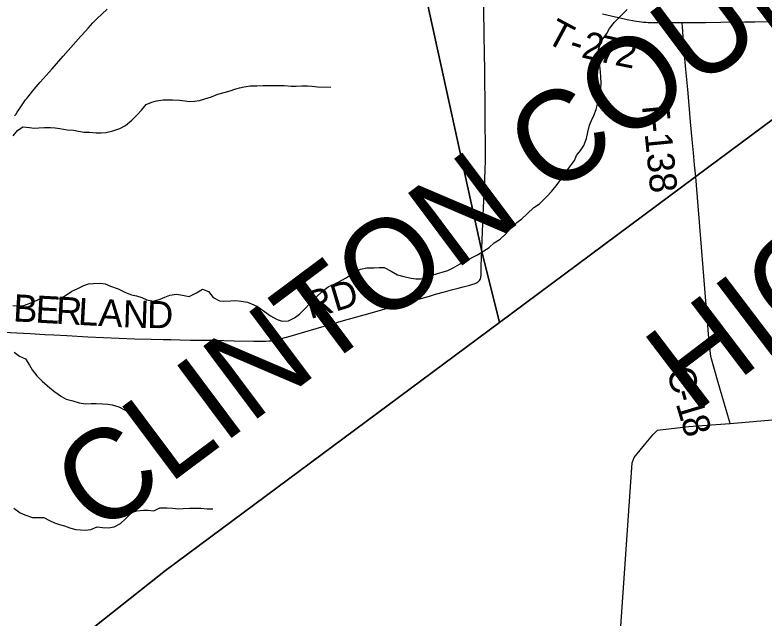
# Model space of a CAD drawing. Extents: x 0 to 48.6, y 0 to 22.
# Drawn here: x 5.524 to 7.09, y 17.154 to 18.416 of the extents above; entities that cross this region are included whole.
import ezdxf

# ---------------------------------------------------------------- set-up
doc = ezdxf.new("R2010")
doc.units = 0
for name, color, linetype in [('GM_X_Corporation', 7, 'Continuous'), ('GM_X_County_Road', 7, 'Continuous'), ('GM_X_County_Road_Text', 7, 'Continuous'), ('GM_X_County_Text', 7, 'Continuous'), ('GM_X_Minor_River', 7, 'Continuous'), ('GM_X_Township_Road', 7, 'Continuous'), ('GM_X_Township_Road_Text', 7, 'Continuous')]:
    doc.layers.add(name, color=color, linetype=linetype)

msp = doc.modelspace()

# ---------------------------------------------------------------- linework, layer by layer
at = {"layer": 'GM_X_Corporation'}
for points in [[(5.5264, 17.0064), (5.8387, 17.2541), (6.5365, 17.7727), (6.4996, 17.9212), (6.3396, 18.6531), (6.2759, 18.9159), (6.0412, 19.8859), (5.8236, 20.7829), (5.795, 20.9), (2.1, 20.9), (2.1, 14.1)], [(5.5264, 17.0064), (5.8387, 17.2541), (6.5365, 17.7727), (6.9471, 18.0777), (7.2261, 18.2847)]]:
    msp.add_lwpolyline(points, dxfattribs=at)
for points in [[(8.9, 19.5692), (8.9, 20.9), (5.795, 20.9), (5.8236, 20.7829), (6.0412, 19.8859), (6.2759, 18.9159), (6.3396, 18.6531), (6.4996, 17.9212), (6.5365, 17.7727), (6.9471, 18.0777), (7.2261, 18.2847), (8.5348, 19.2897)], [(5.0944, 14.1), (8.9, 14.1), (8.9, 19.5692), (8.5348, 19.2897), (7.2261, 18.2847), (6.9471, 18.0777), (6.5365, 17.7727), (5.8387, 17.2541), (5.5264, 17.0064), (4.6225, 16.3345), (4.044, 15.9033), (4.0346, 15.8959), (4.0398, 15.887), (4.3544, 15.3539), (4.4679, 15.1616), (4.7542, 14.6766)]]:
    msp.add_lwpolyline(points, close=True, dxfattribs=at)
at = {"layer": 'GM_X_County_Road'}
for points in [[(7.0193, 17.5612), (6.9943, 17.6472), (6.979, 17.7015), (6.9747, 17.7396), (6.9473, 18.0772)], [(6.2545, 16.2661), (6.3196, 16.2983), (6.3869, 16.3334), (6.4082, 16.3506), (6.4486, 16.3853), (6.4771, 16.4164), (6.644, 16.6404), (6.7584, 16.7938), (6.7668, 16.8095), (6.7711, 16.8557), (6.8142, 17.4789), (6.8183, 17.4898), (6.8434, 17.5207), (6.8575, 17.5377), (6.8672, 17.547), (6.9323, 17.5551), (7.0193, 17.5612), (7.1388, 17.5717)]]:
    msp.add_lwpolyline(points, dxfattribs=at)
at = {"layer": 'GM_X_Minor_River'}
for points in [[(5.8475, 17.8297), (5.8618, 17.8314), (5.874, 17.8298), (5.8883, 17.8266), (5.9032, 17.8348), (5.9158, 17.8419), (5.9287, 17.8373), (5.9384, 17.825), (5.9513, 17.8177), (5.9607, 17.8169), (5.9752, 17.8175), (5.9846, 17.8182), (5.9968, 17.8169), (6.0097, 17.8153), (6.0229, 17.8095), (6.0331, 17.8048), (6.0452, 17.7956), (6.058, 17.7864), (6.0719, 17.779), (6.0825, 17.7751), (6.0958, 17.7762), (6.108, 17.7825), (6.1187, 17.79), (6.1287, 17.7994), (6.1413, 17.8137), (6.1536, 17.8254), (6.1658, 17.8374), (6.1784, 17.8468), (6.1914, 17.8527), (6.2009, 17.8576), (6.2146, 17.865), (6.2261, 17.8721), (6.2368, 17.8789), (6.2463, 17.8837), (6.2592, 17.887), (6.274, 17.8869), (6.2854, 17.8872), (6.296, 17.8875), (6.31, 17.8797), (6.3232, 17.8724), (6.3368, 17.8685), (6.3524, 17.8649), (6.3618, 17.8637), (6.3717, 17.8636), (6.382, 17.8654), (6.3961, 17.8714), (6.4071, 17.8751), (6.417, 17.8776), (6.4291, 17.8809), (6.4402, 17.8869), (6.4543, 17.8951), (6.4658, 17.9015), (6.4783, 17.9078), (6.4909, 17.9138), (6.5043, 17.922), (6.5153, 17.9295), (6.526, 17.9389), (6.5379, 17.9468), (6.5494, 17.9569), (6.5597, 17.969), (6.5731, 17.9817), (6.5834, 17.9892), (6.5945, 17.9998), (6.6087, 18.0129), (6.6201, 18.0208), (6.6358, 18.0362), (6.6454, 18.0464), (6.655, 18.058), (6.665, 18.0716), (6.6723, 18.0814), (6.6792, 18.0916), (6.6938, 18.1112), (6.6981, 18.1214), (6.7065, 18.1324), (6.713, 18.1425), (6.7185, 18.1573), (6.7216, 18.1702), (6.7252, 18.1849), (6.7295, 18.1952), (6.7337, 18.2057), (6.7388, 18.2182), (6.7419, 18.2292), (6.7443, 18.2406), (6.747, 18.2508), (6.7487, 18.2622), (6.7491, 18.2735), (6.7485, 18.2853), (6.7478, 18.2967), (6.7464, 18.3096), (6.745, 18.321), (6.7432, 18.3305), (6.7437, 18.3431), (6.7476, 18.3537), (6.7518, 18.3635), (6.7611, 18.3771), (6.7665, 18.3873), (6.7776, 18.4004), (6.7914, 18.4144), (6.804, 18.4268)], [(5.8532, 18.2384), (5.8674, 18.2375), (5.8791, 18.2359), (5.889, 18.235), (5.8989, 18.2357), (5.9095, 18.2371), (5.9205, 18.2401), (5.9346, 18.2445), (5.9476, 18.2497), (5.9609, 18.2537), (5.9738, 18.257), (5.9833, 18.2604), (5.9932, 18.2629), (6.0027, 18.2655), (6.0156, 18.2677), (6.0297, 18.2675), (6.043, 18.2682), (6.0528, 18.2681), (6.0646, 18.2684), (6.0767, 18.2683), (6.0866, 18.2678), (6.101, 18.2669), (6.112, 18.2664), (6.1234, 18.2671), (6.1352, 18.2673), (6.1454, 18.2669), (6.1564, 18.2656), (6.1845, 18.2646)], [(5.5198, 18.1626), (5.529, 18.1743), (5.5405, 18.1817), (5.5542, 18.1804), (5.5637, 18.1787), (5.5739, 18.1798), (5.5853, 18.18), (5.5979, 18.1802), (5.6081, 18.1793), (5.6176, 18.1784), (5.6327, 18.1752), (5.6464, 18.175), (5.6563, 18.1726), (5.6684, 18.1702), (5.6794, 18.1704), (5.6938, 18.1691), (5.7041, 18.169), (5.714, 18.17), (5.7281, 18.1736), (5.7433, 18.1783), (5.7548, 18.1846), (5.7682, 18.1955), (5.7783, 18.2063), (5.7883, 18.2168), (5.7983, 18.2281), (5.8101, 18.2333), (5.8197, 18.2362), (5.8334, 18.2383), (5.8532, 18.2384)], [(5.5196, 17.8077), (5.5317, 17.8075), (5.5424, 17.8081), (5.5592, 17.814), (5.5702, 17.8192), (5.5821, 17.8251), (5.5927, 17.8253), (5.6052, 17.8221), (5.6189, 17.8223), (5.6296, 17.8286), (5.6423, 17.8383), (5.6549, 17.8435), (5.6679, 17.8498), (5.6774, 17.8531), (5.6881, 17.8541), (5.7025, 17.855), (5.7124, 17.8534), (5.7237, 17.8483), (5.7392, 17.8428), (5.7535, 17.8358), (5.7671, 17.8306), (5.7777, 17.8279), (5.7887, 17.8247), (5.7993, 17.82), (5.8137, 17.8168), (5.827, 17.8215), (5.837, 17.8252), (5.8475, 17.8297)], [(5.5224, 17.7101), (5.533, 17.7023), (5.5458, 17.6965), (5.554, 17.6831), (5.5595, 17.6735), (5.5693, 17.6609), (5.5805, 17.6497), (5.5963, 17.6358), (5.6068, 17.6277), (5.6211, 17.6177), (5.6309, 17.6122), (5.6445, 17.6086), (5.6578, 17.6043), (5.6714, 17.6026), (5.6832, 17.6028), (5.6938, 17.6031), (5.7075, 17.6021), (5.7177, 17.6016), (5.7272, 17.6004), (5.7408, 17.5964), (5.7544, 17.5894), (5.7665, 17.5866)], [(5.5215, 17.3844), (5.5346, 17.3743), (5.5445, 17.37), (5.5607, 17.3645), (5.5733, 17.3647), (5.5843, 17.3646), (5.5959, 17.358), (5.6065, 17.3536), (5.6167, 17.3497), (5.6273, 17.3469), (5.6383, 17.343), (5.6504, 17.3394), (5.6606, 17.3389), (5.6713, 17.3384), (5.6827, 17.3397), (5.6953, 17.3449), (5.7071, 17.344), (5.7192, 17.3431), (5.7314, 17.3448), (5.7444, 17.3519), (5.7551, 17.3616), (5.7679, 17.3751), (5.7782, 17.3787), (5.7922, 17.3801), (5.8021, 17.3796), (5.8142, 17.3783), (5.8265, 17.3846), (5.8413, 17.3845)], [(5.8413, 17.3845), (5.8528, 17.384), (5.8657, 17.3824), (5.8756, 17.3834), (5.8885, 17.384), (5.8995, 17.3843), (5.9124, 17.3838), (5.9253, 17.3826), (5.9374, 17.3828)]]:
    msp.add_lwpolyline(points, dxfattribs=at)
at = {"layer": 'GM_X_Township_Road'}
for points in [[(6.4999, 17.9207), (6.5002, 17.9274), (6.503, 17.997), (6.5043, 18.0274), (6.5051, 18.0521), (6.5059, 18.0645), (6.5064, 18.0744), (6.507, 18.0906), (6.5077, 18.1129), (6.5077, 18.1199), (6.5077, 18.1421), (6.5071, 18.1893), (6.5067, 18.2409), (6.5063, 18.2732), (6.506, 18.2949), (6.5051, 18.3409), (6.5048, 18.367), (6.5038, 18.4347), (6.5035, 18.4639), (6.503, 18.5086), (6.5031, 18.5229), (6.5032, 18.5391), (6.5032, 18.5489)], [(5.5227, 18.2047), (5.5253, 18.2078), (5.5285, 18.2122), (5.532, 18.2173), (5.5399, 18.2298), (5.5429, 18.2339), (5.5458, 18.2379), (5.5482, 18.241), (5.5503, 18.2438), (5.5533, 18.2474), (5.5641, 18.2607), (5.5763, 18.2748), (5.6013, 18.3032), (5.6248, 18.3297), (5.6511, 18.3595), (5.6618, 18.3715), (5.6709, 18.3818), (5.6766, 18.3883), (5.6867, 18.3994), (5.6949, 18.4079), (5.7162, 18.4278)], [(6.9186, 18.3989), (6.8896, 18.3989), (6.8573, 18.3991), (6.8522, 18.3993), (6.8474, 18.3995), (6.8427, 18.3998), (6.8381, 18.4002), (6.8338, 18.4007), (6.8288, 18.4013), (6.8233, 18.4022), (6.8184, 18.403), (6.8038, 18.4058), (6.7522, 18.4171)], [(7.1632, 18.4013), (7.1535, 18.4013), (7.1101, 18.4011), (7.071, 18.4006), (7.0499, 18.4004), (6.9996, 18.3996), (6.9673, 18.399), (6.9387, 18.3989), (6.9186, 18.3989)], [(6.9473, 18.0772), (6.9446, 18.1023), (6.9424, 18.1276), (6.9397, 18.1554), (6.9365, 18.1919), (6.9339, 18.2185), (6.9303, 18.26), (6.9266, 18.3014), (6.9246, 18.3249), (6.9207, 18.3701), (6.9192, 18.3911), (6.9186, 18.3989)], [(5.5001, 17.7525), (5.5552, 17.7492), (5.5862, 17.7475), (5.6049, 17.7465), (5.6321, 17.745), (5.6762, 17.7426), (5.7414, 17.7397), (5.7743, 17.7384), (5.8085, 17.7376), (5.8333, 17.7368), (5.8494, 17.7366), (5.8681, 17.7361), (5.8904, 17.7356), (5.9047, 17.7358), (5.9153, 17.7357), (5.9395, 17.7352), (5.9817, 17.7344), (6.0227, 17.7335), (6.0426, 17.7333), (6.0488, 17.7336), (6.0544, 17.7339), (6.0596, 17.7343), (6.0649, 17.7351), (6.0688, 17.7359), (6.0734, 17.7368), (6.0777, 17.7379), (6.0813, 17.7388), (6.0992, 17.7439), (6.1415, 17.7564), (6.2107, 17.7764), (6.2538, 17.7887), (6.2861, 17.7977), (6.3482, 17.8156), (6.3702, 17.8221), (6.3906, 17.8278), (6.4031, 17.8315), (6.4216, 17.8368), (6.4366, 17.8409), (6.4504, 17.8446), (6.4606, 17.8472), (6.4745, 17.8508), (6.4813, 17.8526), (6.484, 17.8535), (6.487, 17.8546), (6.4888, 17.8555), (6.4908, 17.8567), (6.4923, 17.8577), (6.4938, 17.8591), (6.495, 17.8605), (6.4961, 17.8623), (6.4969, 17.8642), (6.4976, 17.8666), (6.4981, 17.8686), (6.4984, 17.8708), (6.4985, 17.8734), (6.4987, 17.8759), (6.4987, 17.8821), (6.4988, 17.8877), (6.4994, 17.9113), (6.4999, 17.9207)]]:
    msp.add_lwpolyline(points, dxfattribs=at)

# ---------------------------------------------------------------- texts
at = {"layer": 'GM_X_County_Road_Text'}
for s, rotation, p in [('C', 285.2688, (6.8857, 17.6718)), ('-', 286.2693, (6.8982, 17.6258)), ('1', 286.7937, (6.9049, 17.6028)), ('8', 287.0448, (6.9151, 17.5691))]:
    msp.add_text(s, height=0.0568, rotation=rotation, dxfattribs=at).set_placement(p)
at = {"layer": 'GM_X_County_Text'}
for s, rotation, p in [('HIGHLAND COUNTY', 37.2438, (6.9412, 17.5789)), ('CLINTON COUNTY', 36.7754, (5.6985, 17.3231))]:
    msp.add_text(s, height=0.189394, rotation=rotation, dxfattribs=at).set_placement(p)
at = {"layer": 'GM_X_Township_Road_Text'}
for s, height, rotation, p in [('T', 0.0568, 331.7884, (6.6309, 18.3602)), ('2', 0.0568, 346.8676, (6.7059, 18.3274)), ('7', 0.0568, 347.2827, (6.7404, 18.3193)), ('-', 0.0568, 342.5736, (6.6791, 18.3356)), ('2', 0.0568, 348.7347, (6.7761, 18.3113)), ('T-138', 0.05682, 275.6002, (6.8333, 18.2388)), ('RD', 0.05682, 16.5575, (6.141, 17.7792)), ('B', 0.0568, 356.8643, (5.519, 17.775)), ('E', 0.0568, 356.8719, (5.5656, 17.7724)), ('R', 0.0568, 356.8643, (5.6081, 17.7701)), ('L', 0.0568, 356.8719, (5.6547, 17.7676)), ('A', 0.0568, 356.9901, (5.6972, 17.7652)), ('N', 0.0568, 358.1047, (5.7484, 17.7626)), ('D', 0.0568, 359.2924, (5.7996, 17.7609))]:
    msp.add_text(s, height=height, rotation=rotation, dxfattribs=at).set_placement(p)

doc.saveas('drawing.dxf')
